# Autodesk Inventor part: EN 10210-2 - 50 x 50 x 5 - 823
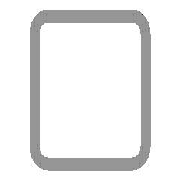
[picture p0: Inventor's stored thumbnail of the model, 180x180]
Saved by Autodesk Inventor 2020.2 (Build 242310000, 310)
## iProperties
IsCustomPart: 1
_CCFamilyMember: 16
_CCFamilyDisplayName: DIN EN 10210-2 (USAS B17.1 quadratisch) - Rohrleitung — In Klammern angegebene Größen wurden aufgehoben
_FrameMemberDoc: Frame Member File
_Version: 15.0.0
_GetPNFromCC: 1
Created: 2019-01
Part Number: EN 10210-2 - 50 x 50 x 5 - 823
Material: Stahl, weich
Description: Rohrleitung
Document SubType Name: Modeling
Standard: DIN
Designer: lutzd
Standard Revision: 2006-07
Standards Organization: DIN
Language: de-DE
Size Designation: 50 x 50 x 5
Categories: <MemberInstance><Categories><Category DisplayName="Profile" InternalName="089c4875-fa83-4c05-b084-43b9cc11f5ed" Mnemonic="GRDR"><CategoryParameter DisplayName="
Stock Number: 50 x 50 x 5
Mass: 5641.19 g
Surface Area: 2803.65 cm^2
Volume: 718.623 cm^3
Density: 7.85 g/cm^3
Appearance: Semi-Polished(8)
G_L: 823,000 mm
G_W: 50,000 mm
G_H: 50,000 mm
DocNumber: ADSK-014263
Folder: .
Dimensions: 50x50x823 mm
Mass: 5,641 kg
+36A53EFA-094D-41AA-9FD8-4C4D03494154+SCHNITTDETAIL1: Schnittwinkel 90,00 grd
+E9FE2E1B-52E9-4794-B0CA-4D34B197932B+SCHNITTDETAIL2: Schnittwinkel 90,00 grd
VLT_Material: Stahl, weich
Title: Profil-Bauteil
Author: lutzd
Revision Number: -
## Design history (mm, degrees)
node "Startebene"
node "Endebene"
sketch "Skizze"
  geometry: L1 (-25, -17.5)-(-25, 17.5); L2 (-17.5, 25)-(17.5, 25); L3 (25, 17.5)-(25, -17.5); L4 (17.5, -25)-(-17.5, -25); L5 (-15, 20)-(15, 20); L6 (20, 15)-(20, -15); L7 (15, -20)-(-15, -20); L8 (-20, -15)-(-20, 15); L9 (0, 37.175)-(0, -37.175) reference; L10 (-37.175, 0)-(37.175, 0) reference; A1 r 7.5 centre (-17.5, -17.5) between (-25, -17.5) and (-17.5, -25); A2 r 7.5 centre (-17.5, 17.5) between (-17.5, 25) and (-25, 17.5); A3 r 7.5 centre (17.5, 17.5) between (25, 17.5) and (17.5, 25); A4 r 7.5 centre (17.5, -17.5) between (17.5, -25) and (25, -17.5); A5 r 5 centre (-15, -15) between (-20, -15) and (-15, -20); A6 r 5 centre (-15, 15) between (-15, 20) and (-20, 15); A7 r 5 centre (15, 15) between (20, 15) and (15, 20); A8 r 5 centre (15, -15) between (15, -20) and (20, -15)
  constraints: 16 end point, 16 point on circle, 16 tangent, 8 centre point, 6 equal radius, 4 parallel, 2 perpendicular, 2 other
  dimensions: "d7" = 7.5 radius of A1 (= G_IR); "d10" = 50 distance between parallel lines of L2 L4 (= G_H); "d11" = 50 distance between parallel lines of L1 L3 (= G_W); "d12" = 5 distance between parallel lines of L3 L6 (= G_T); "d15" = 25 distance between parallel lines of L2 L10 (= 0.5 x d10); "d16" = 25 distance between parallel lines of L9 L3 (= 0.5 x d11); "d19" = 5 radius of A5 (= G_T); "d20" = 5 distance between parallel lines of L4 L7 (= G_T)
extrude "Körper" new body sketch "Skizze" stored distance "d3" = 823 (= G_L); taper "d4" = 0 deg
node "Driven Length"
  sketch "Sketch3"
    geometry: L1 (0, 0)-(10, 0) reference
    constraints: 2 end point, 1 horizontal
  workplane "Work Plane3"
  sketch "Sketch4"
    geometry: L1 (-2, 50)-(12, 50) reference; L2 (-2, 873)-(12, 873) reference
    dimensions: "d18" = 823 distance between parallel lines of L1 L2 (derived)
workplane "Arbeitsebene4"
feature "Trennen1"
workplane "Arbeitsebene5"
feature "Trennen2"
body "Solid1"
other parameters: "G_W" = 50 [user parameter; used in 1 equation term], "G_H" = 50 [user parameter; used in 1 equation term], "G_T" = 5 [user parameter; used in 3 equation terms], "G_IR" = 7.5 [user parameter; used in 1 equation term], "G_L" = 823 (= d18) [user parameter; used in 1 equation term], "G_OFFSET_END" = -35 [user parameter; used in 1 equation term], "d14" = 873 (= G_OFFSET_END + B_L), "B_L" = 908 [user parameter; used in 1 equation term], "d17" = 90 deg
